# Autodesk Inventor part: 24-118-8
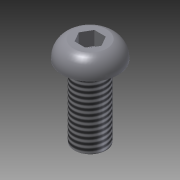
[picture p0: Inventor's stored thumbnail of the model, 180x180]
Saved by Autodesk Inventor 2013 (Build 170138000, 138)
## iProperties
Created: 2004-10
Part Number: 24-118-8
Material: Stahl (hohe Festigk., niedr. Legier.)
Document SubType Name: Modeling
Designer: Autodesk, Inc.
Manufacturer: Standard
Standards Organization: Custom
Description: SCREW, PARKER IPS, BUTTON HEAD, M8X18
Catalog Web Link: http://www.parker.com/ead/cm1.asp?cmid=809
Vendor: PARKER IPS
Mass: 10.8823 g
Surface Area: 9.37524 cm^2
Volume: 1.38805 cm^3
Density: 7.84 g/cm^3
CAGE: 1LJX3
Dept. ID: Product Design
Description #2: ---
Finish #1: ---
Finish #2: ---
Material ID: ---
Project Number: ---
Author: Autodesk, Inc.
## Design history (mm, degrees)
derived "2X-YYY-ZZ IPS Screws.ipt"
body "Solid1"
tag "TaggingFeature2"
feature "Solid1::2X-YYY-ZZ IPS Screws.ipt" dims "ScaleForDerivedMember" = 10
